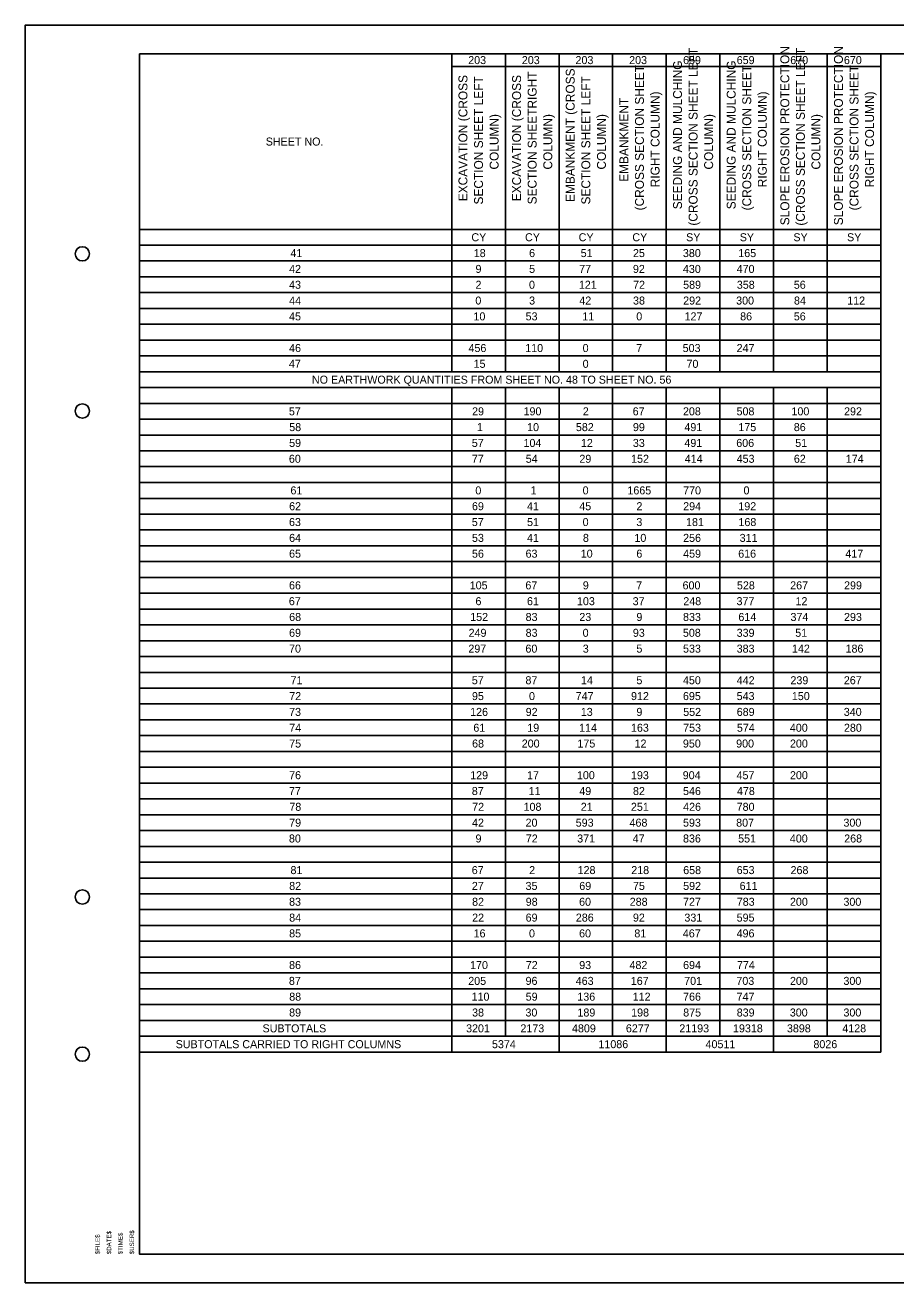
# Model space of a CAD drawing. Extents: x -16 to 102, y -13 to 9.
# Drawn here: x -16.37 to -1.15, y -12.91 to 9.09 of the extents above; entities that cross this region are included whole.
import ezdxf

# ---------------------------------------------------------------- set-up
doc = ezdxf.new("R2010")
doc.units = 0
for name, color, linetype in [('PV_P_EOP', 7, 'Continuous'), ('SH_Border', 7, 'Continuous'), ('SH_Cut_Line', 7, 'Continuous'), ('SH_Data', 7, 'Continuous'), ('TX_P_1', 7, 'Continuous'), ('TX_P_Misc', 7, 'Continuous')]:
    doc.layers.add(name, color=color, linetype=linetype)

msp = doc.modelspace()

# ---------------------------------------------------------------- linework, layer by layer
at = {"layer": 'SH_Border'}
msp.add_lwpolyline([(-14.371, 8.593), (17.129, 8.593), (17.129, -12.407), (-14.371, -12.407)], close=True, dxfattribs=at)
for centre in [(-15.371, 5.093), (-15.371, 2.343), (-15.371, -6.157), (-15.371, -8.907)]:
    msp.add_circle(centre, 0.125, dxfattribs=at)
at = {"layer": 'SH_Cut_Line'}
msp.add_lwpolyline([(-16.371, -12.907), (17.629, -12.907), (17.629, 9.093), (-16.371, 9.093)], close=True, dxfattribs=at)
at = {"layer": 'SH_Data'}
for p, q in [((-14.371, 8.593), (-1.41, 8.593)), ((-14.371, 8.593), (-14.371, -8.87)), ((-8.913, 8.593), (-8.913, 3.03)), ((-7.975, 8.593), (-7.975, 3.03)), ((-7.037, 8.593), (-7.037, 3.03)), ((-6.1, 8.593), (-6.1, 3.03)), ((-5.162, 8.593), (-5.162, 3.03)), ((-4.224, 8.593), (-4.224, 3.03)), ((-3.286, 8.593), (-3.286, 3.03)), ((-2.348, 8.593), (-2.348, 3.03)), ((-1.41, 8.593), (-1.41, -8.87)), ((-8.913, 8.372), (-1.41, 8.372)), ((-14.371, 5.521), (-1.41, 5.521)), ((-14.371, 5.244), (-1.41, 5.244)), ((-14.371, 4.968), (-1.41, 4.968)), ((-14.371, 4.691), (-1.41, 4.691)), ((-14.371, 4.414), (-1.41, 4.414)), ((-14.371, 4.137), (-1.41, 4.137)), ((-14.371, 3.861), (-1.41, 3.861)), ((-14.371, 3.584), (-1.41, 3.584)), ((-14.371, 3.307), (-1.41, 3.307)), ((-14.371, 3.03), (-1.41, 3.03)), ((-14.371, 2.754), (-1.41, 2.754)), ((-8.913, 2.754), (-8.913, -8.87)), ((-7.975, 2.754), (-7.975, -8.593)), ((-7.037, 2.754), (-7.037, -8.87)), ((-6.1, 2.754), (-6.1, -8.593)), ((-5.162, 2.754), (-5.162, -8.87)), ((-4.224, 2.754), (-4.224, -8.593)), ((-3.286, 2.754), (-3.286, -8.87)), ((-2.348, 2.754), (-2.348, -8.593)), ((-14.371, 2.477), (-1.41, 2.477)), ((-14.371, 2.2), (-1.41, 2.2)), ((-14.371, 1.923), (-1.41, 1.923)), ((-14.371, 1.647), (-1.41, 1.647)), ((-14.371, 1.37), (-1.41, 1.37)), ((-14.371, 1.093), (-1.41, 1.093)), ((-14.371, 0.816), (-1.41, 0.816)), ((-14.371, 0.54), (-1.41, 0.54)), ((-14.371, 0.263), (-1.41, 0.263)), ((-14.371, -0.014), (-1.41, -0.014)), ((-14.371, -0.291), (-1.41, -0.291)), ((-14.371, -0.567), (-1.41, -0.567)), ((-14.371, -0.844), (-1.41, -0.844)), ((-14.371, -1.121), (-1.41, -1.121)), ((-14.371, -1.398), (-1.41, -1.398)), ((-14.371, -1.674), (-1.41, -1.674)), ((-14.371, -1.951), (-1.41, -1.951)), ((-14.371, -2.228), (-1.41, -2.228)), ((-14.371, -2.505), (-1.41, -2.505)), ((-14.371, -2.781), (-1.41, -2.781)), ((-14.371, -3.058), (-1.41, -3.058)), ((-14.371, -3.335), (-1.41, -3.335)), ((-14.371, -3.612), (-1.41, -3.612)), ((-14.371, -3.888), (-1.41, -3.888)), ((-14.371, -4.165), (-1.41, -4.165)), ((-14.371, -4.442), (-1.41, -4.442)), ((-14.371, -4.719), (-1.41, -4.719)), ((-14.371, -4.995), (-1.41, -4.995)), ((-14.371, -5.272), (-1.41, -5.272)), ((-14.371, -5.549), (-1.41, -5.549)), ((-14.371, -5.826), (-1.41, -5.826)), ((-14.371, -6.102), (-1.41, -6.102)), ((-14.371, -6.379), (-1.41, -6.379)), ((-14.371, -6.656), (-1.41, -6.656)), ((-14.371, -6.933), (-1.41, -6.933)), ((-14.371, -7.209), (-1.41, -7.209)), ((-14.371, -7.486), (-1.41, -7.486)), ((-14.371, -7.763), (-1.41, -7.763)), ((-14.371, -8.04), (-1.41, -8.04)), ((-14.371, -8.316), (-1.41, -8.316)), ((-14.371, -8.593), (-1.41, -8.593)), ((-14.371, -8.87), (-1.41, -8.87))]:
    msp.add_line(p, q, dxfattribs=at)

# ---------------------------------------------------------------- texts
at = {"layer": 'PV_P_EOP'}
for s, height, p in [('SHEET NO.', 0.14, (-12.165, 6.987)), ('SUBTOTALS', 0.14, (-12.221, -8.525)), ('SUBTOTALS CARRIED TO RIGHT COLUMNS', 0.14004, (-13.74, -8.802))]:
    msp.add_text(s, height=height, dxfattribs=at).set_placement(p)
at = {"layer": 'TX_P_1'}
for s, p in [('(CROSS SECTION SHEET LEFT', (-4.615, 5.586)), ('SLOPE EROSION PROTECTION', (-3.011, 5.593)), ('(CROSS SECTION SHEET LEFT', (-2.739, 5.586)), ('SLOPE EROSION PROTECTION', (-2.074, 5.593)), ('(CROSS SECTION SHEET', (-5.553, 5.853)), ('SEEDING AND MULCHING', (-4.887, 5.873)), ('SEEDING AND MULCHING', (-3.949, 5.873)), ('(CROSS SECTION SHEET', (-3.677, 5.853)), ('(CROSS SECTION SHEET', (-1.801, 5.853)), ('EXCAVATION (CROSS', (-8.639, 6.013)), ('SECTION SHEET LEFT', (-8.366, 5.956)), ('EXCAVATION (CROSS', (-7.701, 6.013)), ('SECTION SHEETRIGHT', (-7.429, 5.958)), ('EMBANKMENT (CROSS', (-6.763, 6)), ('SECTION SHEET LEFT', (-6.491, 5.956)), ('RIGHT COLUMN)', (-5.28, 6.257)), ('RIGHT COLUMN)', (-3.405, 6.257)), ('RIGHT COLUMN)', (-1.529, 6.257)), ('EMBANKMENT', (-5.825, 6.353)), ('COLUMN)', (-8.094, 6.567)), ('COLUMN)', (-7.156, 6.567)), ('COLUMN)', (-6.218, 6.567)), ('COLUMN)', (-4.343, 6.567)), ('COLUMN)', (-2.467, 6.567))]:
    msp.add_text(s, height=0.1556, rotation=90, dxfattribs=at).set_placement(p)
for s, height, p in [('203', 0.14, (-8.625, 8.412)), ('203', 0.14, (-7.687, 8.412)), ('203', 0.14, (-6.749, 8.412)), ('203', 0.14, (-5.811, 8.412)), ('659', 0.14, (-4.868, 8.412)), ('659', 0.14, (-3.93, 8.412)), ('670', 0.14, (-2.994, 8.412)), ('670', 0.14, (-2.056, 8.412)), ('CY', 0.14, (-8.569, 5.313)), ('CY', 0.14, (-7.631, 5.313)), ('CY', 0.14, (-6.693, 5.313)), ('CY', 0.14, (-5.755, 5.313)), ('SY', 0.14, (-4.815, 5.313)), ('SY', 0.14, (-3.877, 5.313)), ('SY', 0.14, (-2.939, 5.313)), ('SY', 0.14, (-2.001, 5.313)), ('41', 0.14, (-11.733, 5.036)), ('18', 0.14, (-8.528, 5.036)), ('6', 0.14, (-7.56, 5.036)), ('51', 0.14, (-6.658, 5.036)), ('25', 0.14, (-5.744, 5.036)), ('380', 0.14, (-4.871, 5.036)), ('165', 0.14, (-3.903, 5.036)), ('42', 0.14, (-11.756, 4.759)), ('9', 0.14, (-8.497, 4.759)), ('5', 0.14, (-7.56, 4.759)), ('77', 0.14, (-6.685, 4.759)), ('92', 0.14, (-5.745, 4.759)), ('430', 0.14, (-4.871, 4.759)), ('470', 0.14, (-3.931, 4.759)), ('43', 0.14, (-11.757, 4.482)), ('2', 0.14, (-8.497, 4.482)), ('0', 0.14, (-7.562, 4.482)), ('121', 0.14, (-6.69, 4.482)), ('72', 0.14, (-5.742, 4.482)), ('589', 0.14, (-4.867, 4.482)), ('358', 0.14, (-3.928, 4.482)), ('56', 0.14, (-2.932, 4.482)), ('44', 0.14, (-11.755, 4.206)), ('0', 0.14, (-8.5, 4.206)), ('3', 0.14, (-7.56, 4.206)), ('42', 0.14, (-6.682, 4.206)), ('38', 0.14, (-5.743, 4.206)), ('292', 0.14, (-4.866, 4.206)), ('300', 0.14, (-3.94, 4.206)), ('84', 0.14, (-2.929, 4.206)), ('112', 0.14, (-1.998, 4.206)), ('45', 0.14, (-11.757, 3.929)), ('10', 0.14, (-8.533, 3.929)), ('53', 0.14, (-7.621, 3.929)), ('11', 0.14, (-6.631, 3.929)), ('0', 0.14, (-5.686, 3.929)), ('127', 0.14, (-4.842, 3.929)), ('86', 0.14, (-3.87, 3.929)), ('56', 0.14, (-2.932, 3.929)), ('46', 0.14, (-11.757, 3.375)), ('456', 0.14, (-8.62, 3.375)), ('110', 0.14, (-7.628, 3.375)), ('0', 0.14, (-6.624, 3.375)), ('7', 0.14, (-5.687, 3.375)), ('503', 0.14, (-4.875, 3.375)), ('247', 0.14, (-3.932, 3.375)), ('47', 0.14, (-11.76, 3.099)), ('15', 0.14, (-8.531, 3.099)), ('0', 0.14, (-6.624, 3.099)), ('70', 0.14, (-4.808, 3.099)), ('NO EARTHWORK QUANTITIES FROM SHEET NO. 48 TO SHEET NO. 56', 0.14004, (-11.357, 2.822)), ('57', 0.14, (-11.76, 2.268)), ('29', 0.14, (-8.557, 2.268)), ('190', 0.14, (-7.657, 2.268)), ('2', 0.14, (-6.621, 2.268)), ('67', 0.14, (-5.749, 2.268)), ('208', 0.14, (-4.87, 2.268)), ('508', 0.14, (-3.933, 2.268)), ('100', 0.14, (-2.973, 2.268)), ('292', 0.14, (-2.053, 2.268)), ('58', 0.14, (-11.754, 1.992)), ('1', 0.14, (-8.473, 1.992)), ('10', 0.14, (-7.595, 1.992)), ('582', 0.14, (-6.742, 1.992)), ('99', 0.14, (-5.745, 1.992)), ('491', 0.14, (-4.845, 1.992)), ('175', 0.14, (-3.901, 1.992)), ('86', 0.14, (-2.932, 1.992)), ('59', 0.14, (-11.756, 1.715)), ('57', 0.14, (-8.562, 1.715)), ('104', 0.14, (-7.658, 1.715)), ('12', 0.14, (-6.654, 1.715)), ('33', 0.14, (-5.746, 1.715)), ('491', 0.14, (-4.845, 1.715)), ('606', 0.14, (-3.938, 1.715)), ('51', 0.14, (-2.907, 1.715)), ('60', 0.14, (-11.76, 1.438)), ('77', 0.14, (-8.561, 1.438)), ('54', 0.14, (-7.619, 1.438)), ('29', 0.14, (-6.681, 1.438)), ('152', 0.14, (-5.777, 1.438)), ('414', 0.14, (-4.839, 1.438)), ('453', 0.14, (-3.931, 1.438)), ('62', 0.14, (-2.931, 1.438)), ('174', 0.14, (-2.023, 1.438)), ('61', 0.14, (-11.733, 0.885)), ('0', 0.14, (-8.5, 0.885)), ('1', 0.14, (-7.535, 0.885)), ('0', 0.14, (-6.624, 0.885)), ('1665', 0.14, (-5.841, 0.885)), ('770', 0.14, (-4.867, 0.885)), ('0', 0.14, (-3.811, 0.885)), ('62', 0.14, (-11.756, 0.608)), ('69', 0.14, (-8.559, 0.608)), ('41', 0.14, (-7.597, 0.608)), ('45', 0.14, (-6.683, 0.608)), ('2', 0.14, (-5.683, 0.608)), ('294', 0.14, (-4.866, 0.608)), ('192', 0.14, (-3.902, 0.608)), ('63', 0.14, (-11.758, 0.331)), ('57', 0.14, (-8.562, 0.331)), ('51', 0.14, (-7.596, 0.331)), ('0', 0.14, (-6.624, 0.331)), ('3', 0.14, (-5.685, 0.331)), ('181', 0.14, (-4.816, 0.331)), ('168', 0.14, (-3.9, 0.331)), ('64', 0.14, (-11.756, 0.054)), ('53', 0.14, (-8.559, 0.054)), ('41', 0.14, (-7.597, 0.054)), ('8', 0.14, (-6.619, 0.054)), ('10', 0.14, (-5.719, 0.054)), ('256', 0.14, (-4.867, 0.054)), ('311', 0.14, (-3.879, 0.054)), ('65', 0.14, (-11.757, -0.222)), ('56', 0.14, (-8.559, -0.222)), ('63', 0.14, (-7.622, -0.222)), ('10', 0.14, (-6.657, -0.222)), ('6', 0.14, (-5.685, -0.222)), ('459', 0.14, (-4.867, -0.222)), ('616', 0.14, (-3.904, -0.222)), ('417', 0.14, (-2.03, -0.222)), ('66', 0.14, (-11.758, -0.776)), ('105', 0.14, (-8.598, -0.776)), ('67', 0.14, (-7.625, -0.776)), ('9', 0.14, (-6.621, -0.776)), ('7', 0.14, (-5.687, -0.776)), ('600', 0.14, (-4.877, -0.776)), ('528', 0.14, (-3.926, -0.776)), ('267', 0.14, (-2.995, -0.776)), ('299', 0.14, (-2.053, -0.776)), ('67', 0.14, (-11.761, -1.053)), ('6', 0.14, (-8.498, -1.053)), ('61', 0.14, (-7.597, -1.053)), ('103', 0.14, (-6.723, -1.053)), ('37', 0.14, (-5.749, -1.053)), ('248', 0.14, (-4.864, -1.053)), ('377', 0.14, (-3.933, -1.053)), ('12', 0.14, (-2.902, -1.053)), ('68', 0.14, (-11.755, -1.329)), ('152', 0.14, (-8.59, -1.329)), ('83', 0.14, (-7.621, -1.329)), ('23', 0.14, (-6.682, -1.329)), ('9', 0.14, (-5.684, -1.329)), ('833', 0.14, (-4.869, -1.329)), ('614', 0.14, (-3.901, -1.329)), ('374', 0.14, (-2.99, -1.329)), ('293', 0.14, (-2.054, -1.329)), ('69', 0.14, (-11.757, -1.606)), ('249', 0.14, (-8.618, -1.606)), ('83', 0.14, (-7.621, -1.606)), ('0', 0.14, (-6.624, -1.606)), ('93', 0.14, (-5.746, -1.606)), ('508', 0.14, (-4.871, -1.606)), ('339', 0.14, (-3.931, -1.606)), ('51', 0.14, (-2.907, -1.606)), ('70', 0.14, (-11.757, -1.883)), ('297', 0.14, (-8.622, -1.883)), ('60', 0.14, (-7.624, -1.883)), ('3', 0.14, (-6.622, -1.883)), ('5', 0.14, (-5.684, -1.883)), ('533', 0.14, (-4.869, -1.883)), ('383', 0.14, (-3.931, -1.883)), ('142', 0.14, (-2.964, -1.883)), ('186', 0.14, (-2.027, -1.883)), ('71', 0.14, (-11.731, -2.436)), ('57', 0.14, (-8.562, -2.436)), ('87', 0.14, (-7.624, -2.436)), ('14', 0.14, (-6.653, -2.436)), ('5', 0.14, (-5.684, -2.436)), ('450', 0.14, (-4.87, -2.436)), ('442', 0.14, (-3.93, -2.436)), ('239', 0.14, (-2.991, -2.436)), ('267', 0.14, (-2.057, -2.436)), ('72', 0.14, (-11.754, -2.713)), ('95', 0.14, (-8.559, -2.713)), ('0', 0.14, (-7.562, -2.713)), ('747', 0.14, (-6.746, -2.713)), ('912', 0.14, (-5.778, -2.713)), ('695', 0.14, (-4.87, -2.713)), ('543', 0.14, (-3.931, -2.713)), ('150', 0.14, (-2.966, -2.713)), ('73', 0.14, (-11.756, -2.99)), ('126', 0.14, (-8.591, -2.99)), ('92', 0.14, (-7.62, -2.99)), ('13', 0.14, (-6.656, -2.99)), ('9', 0.14, (-5.684, -2.99)), ('552', 0.14, (-4.866, -2.99)), ('689', 0.14, (-3.93, -2.99)), ('340', 0.14, (-2.058, -2.99)), ('74', 0.14, (-11.754, -3.267)), ('61', 0.14, (-8.535, -3.267)), ('19', 0.14, (-7.592, -3.267)), ('114', 0.14, (-6.686, -3.267)), ('163', 0.14, (-5.779, -3.267)), ('753', 0.14, (-4.867, -3.267)), ('574', 0.14, (-3.927, -3.267)), ('400', 0.14, (-3.001, -3.267)), ('280', 0.14, (-2.055, -3.267)), ('75', 0.14, (-11.755, -3.543)), ('68', 0.14, (-8.557, -3.543)), ('200', 0.14, (-7.689, -3.543)), ('175', 0.14, (-6.715, -3.543)), ('12', 0.14, (-5.716, -3.543)), ('950', 0.14, (-4.871, -3.543)), ('900', 0.14, (-3.94, -3.543)), ('200', 0.14, (-2.999, -3.543)), ('76', 0.14, (-11.756, -4.097)), ('129', 0.14, (-8.59, -4.097)), ('17', 0.14, (-7.596, -4.097)), ('100', 0.14, (-6.724, -4.097)), ('193', 0.14, (-5.779, -4.097)), ('904', 0.14, (-4.874, -4.097)), ('457', 0.14, (-3.933, -4.097)), ('200', 0.14, (-2.999, -4.097)), ('77', 0.14, (-11.759, -4.374)), ('87', 0.14, (-8.562, -4.374)), ('11', 0.14, (-7.568, -4.374)), ('49', 0.14, (-6.683, -4.374)), ('82', 0.14, (-5.744, -4.374)), ('546', 0.14, (-4.869, -4.374)), ('478', 0.14, (-3.926, -4.374)), ('78', 0.14, (-11.752, -4.65)), ('72', 0.14, (-8.556, -4.65)), ('108', 0.14, (-7.657, -4.65)), ('21', 0.14, (-6.657, -4.65)), ('251', 0.14, (-5.78, -4.65)), ('426', 0.14, (-4.867, -4.65)), ('780', 0.14, (-3.931, -4.65)), ('79', 0.14, (-11.755, -4.927)), ('42', 0.14, (-8.558, -4.927)), ('20', 0.14, (-7.622, -4.927)), ('593', 0.14, (-6.745, -4.927)), ('468', 0.14, (-5.804, -4.927)), ('593', 0.14, (-4.869, -4.927)), ('807', 0.14, (-3.94, -4.927)), ('300', 0.14, (-2.064, -4.927)), ('80', 0.14, (-11.759, -5.204)), ('9', 0.14, (-8.497, -5.204)), ('72', 0.14, (-7.618, -5.204)), ('371', 0.14, (-6.719, -5.204)), ('47', 0.14, (-5.749, -5.204)), ('836', 0.14, (-4.869, -5.204)), ('551', 0.14, (-3.905, -5.204)), ('400', 0.14, (-3.001, -5.204)), ('268', 0.14, (-2.051, -5.204)), ('81', 0.14, (-11.732, -5.757)), ('67', 0.14, (-8.563, -5.757)), ('2', 0.14, (-7.559, -5.757)), ('128', 0.14, (-6.712, -5.757)), ('218', 0.14, (-5.774, -5.757)), ('658', 0.14, (-4.866, -5.757)), ('653', 0.14, (-3.931, -5.757)), ('268', 0.14, (-2.989, -5.757)), ('82', 0.14, (-11.755, -6.034)), ('27', 0.14, (-8.561, -6.034)), ('35', 0.14, (-7.622, -6.034)), ('69', 0.14, (-6.683, -6.034)), ('75', 0.14, (-5.744, -6.034)), ('592', 0.14, (-4.867, -6.034)), ('611', 0.14, (-3.879, -6.034)), ('83', 0.14, (-11.757, -6.311)), ('82', 0.14, (-8.557, -6.311)), ('98', 0.14, (-7.619, -6.311)), ('60', 0.14, (-6.686, -6.311)), ('288', 0.14, (-5.801, -6.311)), ('727', 0.14, (-4.869, -6.311)), ('783', 0.14, (-3.929, -6.311)), ('200', 0.14, (-2.999, -6.311)), ('300', 0.14, (-2.064, -6.311)), ('84', 0.14, (-11.755, -6.588)), ('22', 0.14, (-8.556, -6.588)), ('69', 0.14, (-7.621, -6.588)), ('286', 0.14, (-6.743, -6.588)), ('92', 0.14, (-5.745, -6.588)), ('331', 0.14, (-4.845, -6.588)), ('595', 0.14, (-3.931, -6.588)), ('85', 0.14, (-11.756, -6.864)), ('16', 0.14, (-8.531, -6.864)), ('0', 0.14, (-7.562, -6.864)), ('60', 0.14, (-6.686, -6.864)), ('81', 0.14, (-5.72, -6.864)), ('467', 0.14, (-4.872, -6.864)), ('496', 0.14, (-3.932, -6.864)), ('86', 0.14, (-11.757, -7.418)), ('170', 0.14, (-8.592, -7.418)), ('72', 0.14, (-7.618, -7.418)), ('93', 0.14, (-6.684, -7.418)), ('482', 0.14, (-5.805, -7.418)), ('694', 0.14, (-4.868, -7.418)), ('774', 0.14, (-3.926, -7.418)), ('87', 0.14, (-11.76, -7.695)), ('205', 0.14, (-8.624, -7.695)), ('96', 0.14, (-7.622, -7.695)), ('463', 0.14, (-6.745, -7.695)), ('167', 0.14, (-5.782, -7.695)), ('701', 0.14, (-4.849, -7.695)), ('703', 0.14, (-3.936, -7.695)), ('200', 0.14, (-2.999, -7.695)), ('300', 0.14, (-2.064, -7.695)), ('88', 0.14, (-11.754, -7.971)), ('110', 0.14, (-8.566, -7.971)), ('59', 0.14, (-7.62, -7.971)), ('136', 0.14, (-6.717, -7.971)), ('112', 0.14, (-5.749, -7.971)), ('766', 0.14, (-4.868, -7.971)), ('747', 0.14, (-3.932, -7.971)), ('89', 0.14, (-11.756, -8.248)), ('38', 0.14, (-8.557, -8.248)), ('30', 0.14, (-7.624, -8.248)), ('189', 0.14, (-6.715, -8.248)), ('198', 0.14, (-5.776, -8.248)), ('875', 0.14, (-4.866, -8.248)), ('839', 0.14, (-3.93, -8.248)), ('300', 0.14, (-3.002, -8.248)), ('300', 0.14, (-2.064, -8.248)), ('3201', 0.14, (-8.662, -8.525)), ('2173', 0.14, (-7.712, -8.525)), ('4809', 0.14, (-6.81, -8.525)), ('6277', 0.14, (-5.868, -8.525)), ('21193', 0.14, (-4.934, -8.525)), ('19318', 0.14, (-3.995, -8.525)), ('3898', 0.14, (-3.052, -8.525)), ('4128', 0.14, (-2.084, -8.525)), ('5374', 0.14, (-8.209, -8.802)), ('11086', 0.14, (-6.348, -8.802)), ('40511', 0.14, (-4.475, -8.802)), ('8026', 0.14, (-2.589, -8.802))]:
    msp.add_text(s, height=height, dxfattribs=at).set_placement(p)
at = {"layer": 'TX_P_Misc'}
for s, p in [('$FILE$', (-15.067, -12.407)), ('$DATE$', (-14.867, -12.407)), ('$TIME$', (-14.667, -12.407)), ('$USER$', (-14.467, -12.407))]:
    msp.add_text(s, height=0.078, rotation=90, dxfattribs=at).set_placement(p)

doc.saveas('drawing.dxf')
